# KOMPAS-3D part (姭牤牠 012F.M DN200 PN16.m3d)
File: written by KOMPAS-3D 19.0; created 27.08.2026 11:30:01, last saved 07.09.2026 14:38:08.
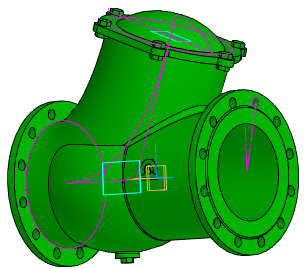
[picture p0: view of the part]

Document properties: Автор: Энергия; Полное имя файла: Z:\3.Личные\kachalov\001_3d для проектировщиков\х.х Тип 012F\012F.M\Клапан 012F.M DN200 PN16.m3d

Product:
- Part/product: (unnamed)  | designation Клапан 012F.M DN200 PN16
    Масса: 203.986

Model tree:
1. Эскиз:1
2. Элемент вращения:1
     Угол 1 = 360
3. Эскиз:2  (with: Элемент вращения:1)
4. Перпендикулярная плоскость:1
5. Эскиз:3
6. Эскиз:12  (with: Элемент вращения:1)
7. Элемент по сечениям:1
8. Эскиз:7
9. Элемент выдавливания:2
     Расстояние 2 = 15
10. Эскиз:9  (with: Элемент выдавливания:2)
11. Элемент вращения:2
     Угол 1 = 360
12. Эскиз:10  (with: Элемент вращения:1)
13. Элемент выдавливания:3  (with: Элемент вращения:1)
     Расстояние 2 = 17
14. Массив по концентрической сетке:1  (with: Элемент выдавливания:3, Эскиз:10, Элемент вращения:1)  (12 pattern instances)
     Шаг 2 = 360
15. Эскиз:11  (with: Элемент вращения:1)
16. Элемент выдавливания:4  (with: Элемент вращения:1)
     Расстояние 2 = 17
17. Массив по концентрической сетке:2  (with: Элемент выдавливания:4, Эскиз:11, Элемент вращения:1)  (12 pattern instances)
     Шаг 2 = 360
18. Скругление:6  (with: Элемент выдавливания:2)
     Радиус = 3
19. Эскиз:13  (with: Элемент выдавливания:2)
20. Элемент выдавливания:5  (with: Элемент выдавливания:2)
     Расстояние 1 = 10; Смещение 2 = 10
21. Массив по концентрической сетке:3  (with: Элемент выдавливания:5, Эскиз:9, Эскиз:13, Элемент вращения:2)  (6 pattern instances)
     Шаг 2 = 360
22. Касательная плоскость:1  (with: Элемент вращения:1)
     Угол = 90
23. Смещенная плоскость:1
     Расстояние = 2
24. Эскиз:14
25. Элемент выдавливания:6  (with: Элемент вращения:1)
     Расстояние 1 = -2.24729; Расстояние 2 = 1
26. Эскиз:15  (with: Элемент вращения:1)
27. Элемент вращения:3
     Угол 1 = 360
28. Скругление:10  (with: Элемент вращения:3, Элемент по сечениям:1)
     Радиус = 10
29. Эскиз:16
30. Элемент выдавливания:7
     Расстояние 1 = 160
31. Эскиз:17  (with: Элемент выдавливания:7)
32. Элемент выдавливания:8
     Расстояние 1 = 10
33. Эскиз:18  (with: Элемент вращения:1)
34. Элемент выдавливания:9
     Расстояние 2 = 500
35. Скругление:12  (with: Элемент выдавливания:7)
     Радиус = 3

Expressions: Dn/2; D/2; D2/2; D2/2-5; 360/(2*n); 360/(n*2); D2-6; D2-5; 340/2
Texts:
  Клапан 012F.M DN200 PN16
